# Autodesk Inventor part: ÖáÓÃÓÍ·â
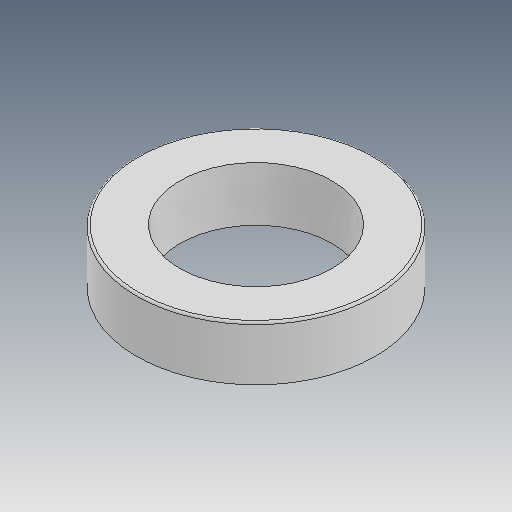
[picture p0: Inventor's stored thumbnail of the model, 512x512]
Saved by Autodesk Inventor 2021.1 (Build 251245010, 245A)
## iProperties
Created: 2019-04
Part Number: ÖáÓÃÓÍ·â
Material: Ogólny
Document SubType Name: Modeling
Designer: user
Density: 1 g/cm^3
Appearance: Domyślna
Author: user
Revision Number: ÈÎºÎ
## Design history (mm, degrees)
feature "ÊäÈë1"
node "Bryła1"
